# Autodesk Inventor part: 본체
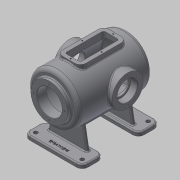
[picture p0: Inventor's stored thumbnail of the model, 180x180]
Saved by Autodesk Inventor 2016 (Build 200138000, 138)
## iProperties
Created: 2016-02
Part Number: 본체
Material: 일반
Document SubType Name: Modeling
Designer: mduedu
Density: 1 g/cm^3
Appearance: 기본값
Author: mduedu
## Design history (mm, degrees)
sketch "스케치2"
  geometry: L1 (0, 100)-(0, -100); L2 (65, -87.083)-(65, 100); L3 (65, 100)-(0, 100); A1 r 170 centre (0, 70) between (0, -100) and (65, -87.083); 2 further points
  constraints: 6 end point, 2 point on circle, 1 centre point, 1 coincident, 1 horizontal, 1 midpoint, 1 parallel, 1 point on line, 1 vertical
  dimensions: "d3" = 200 distance of L1.start L1.end; "d5" = 130 diameter of L2 L1; "d6" = 170 radius of A1
revolve "회전1" sketch "스케치2" stored, may be unused: angle "d7" = 90 deg
sketch "스케치3"
  geometry: C1 r 47.5 at (0, 0); 1 further point
  constraints: 1 centre point, 1 coincident
  dimensions: "d8" = 95 diameter of C1
extrude "돌출2" join sketch "스케치3" distance "d10" = 10; taper "d11" = 0 deg
sketch "스케치5"
  geometry: L1 (47.5, 110)-(47.5, 100) reference; L2 (47.5, 100)-(65, 100) reference; L3 (65, 100)-(65, -87.083) reference; L4 (-65, -87.083)-(-65, 100) reference; L5 (-65, 100)-(-47.5, 100) reference; L6 (-47.5, 100)-(-47.5, 110) reference; L7 (-47.5, 110)-(47.5, 110) reference; L8 (55, 85)-(55, -80.25); L9 (0, 85)-(55, 85); L10 (0, 85)-(0, -90); A1 r 170 centre (0, 70) between (-65, -87.083) and (0, -100) reference; A2 r 170 centre (0, 70) between (0, -100) and (65, -87.083) reference; A3 r 160 centre (0, 70) between (0, -90) and (55, -80.25); 1 further point
  constraints: 6 end point, 2 point on circle, 1 centre point, 1 parallel, 1 perpendicular, 1 point on line, 1 vertical
  dimensions: "d13" = 10 distance between parallel lines of L3 L8; "d14" = 10 radial gap between concentric circles of A3 A1; "d15" = 15 distance between parallel lines of L9 L2
revolve "회전2" sketch "스케치5" stored, may be unused: angle "d16" = 90 deg
hole "구멍1" diameter "d19" = 65; stored, may be unused: countersink angle "d23" = 90 deg, drill point angle "d25" = 118 deg; dims "d17" = 10, "d18" = 10, "d20" = 6, "d21" = 4, "d22" = 2, "d24" = 8
node "작업 평면1"
sketch "스케치6"
  geometry: L1 (47.5, 110)-(-47.5, 110) reference; C1 r 40 at (0, -17); 1 further point
  constraints: 1 centre point, 1 vertical alignment
  dimensions: "d27" = 80 diameter of C1; "d29" = 127 distance from line of C1.centre L1
extrude "돌출3" join sketch "스케치6" stored distance "d30" = 10; taper "d31" = 0 deg
hole "구멍2" diameter "d34" = 42; stored, may be unused: countersink angle "d38" = 90 deg, drill point angle "d40" = 118 deg; dims "d32" = 10, "d33" = 10, "d35" = 6, "d36" = 52, "d37" = 18, "d39" = 8
sketch "스케치7" dims "d41" = 65
  geometry: C1 r 40 at (0, 0) reference; 3 further points
  constraints: 2 vertical alignment, 1 coincident, 2 other
hole "구멍3" sketch "스케치7" at (0, 32.5) diameter "d43" = 3.242; stored, may be unused: countersink angle "d47" = 90 deg, drill point angle "d49" = 118 deg; dims "d44" = 11, "d45" = 13, "d46" = 18, "d48" = 13
sketch "스케치8" dims "d53" = 80
  geometry: 3 further points
  constraints: 2 vertical alignment, 1 coincident, 2 other
hole "구멍4" sketch "스케치8" at (0, 40) diameter "d56" = 3.242; stored, may be unused: countersink angle "d60" = 90 deg, drill point angle "d62" = 118 deg; dims "d57" = 11, "d58" = 13, "d59" = 18, "d61" = 13
fillet "모깎기1" dims "d66" = 10
fillet "모깎기2" dims "d67" = 3
fillet "모깎기3" dims "d68" = 0.3
chamfer "모따기1" distance "d69" = 1; stored, may be unused: second distance "d70" = 2, angle "d71" = 45 deg
node "작업 평면2"
sketch "스케치9"
  geometry: L1 (75, 100)-(-75, 100); L2 (-75, 100)-(-75, -100); L3 (-75, -100)-(75, -100); L4 (75, -100)-(75, 100); 1 further point
  constraints: 8 end point, 2 parallel, 1 horizontal, 1 perpendicular
  dimensions: "d73" = 200 distance of L3.end L1.start; "d75" = 150 distance of L2.end L3.end; "d76" = 100 distance from line of L1 point (0, 0); "d77" = 75 distance from line of L4 point (0, 0)
extrude "돌출4" join sketch "스케치9" distance "d78" = 10; taper "d79" = 0 deg
sketch "스케치10"
  geometry: L1 (-75, -100)-(75, -100) reference; L2 (75, 100)-(-75, 100) reference; L3 (0, -100)-(0, 100); L4 (-75, 100)-(-75, -100) reference; L5 (75, -100)-(75, 100) reference; L6 (-75, 0)-(75, 0); L7 (-50, -63)-(50, -63); L8 (50, -63)-(50, -55); L9 (50, -55)-(-50, -55); L10 (-50, -55)-(-50, -63); L11 (-50, 63)-(50, 63); L12 (50, 63)-(50, 55); L13 (50, 55)-(-50, 55); L14 (-50, 55)-(-50, 63); 1 further point
  constraints: 20 end point, 4 midpoint, 4 symmetric about line, 2 parallel, 1 horizontal, 1 perpendicular, 1 other
  dimensions: "d80" = 8 distance of L9.end L7.start; "d82" = 100 distance of L7.start L7.end; "d83" = 55 distance between parallel lines of L9 L6
extrude "돌출5" join sketch "스케치10" stored distance "d84" = 10; taper "d85" = 0 deg
feature "면 기울기1" dims angle "d86" = 10 deg
sketch "스케치11"
  geometry: L1 (-110, 55)-(-51.482, 55) reference; L2 (-110, -55)-(-51.482, -55) reference; L3 (-95, 55)-(-95, -55); L4 (-65, 90)-(-65, -80.25) reference; 1 further point
  constraints: 2 end point, 2 point on line, 1 perpendicular
  dimensions: "d87" = 30 distance between parallel lines of L3 L4
feature "리브1" sketch "스케치11" dims "d88" = 1, "d89" = 8, "d90" = 0, "d91" = 0, "d92" = 1, "d93" = 1
sketch "스케치12"
  geometry: L1 (-110, 55)-(-51.482, 55) reference; L2 (-110, -55)-(-51.482, -55) reference; L3 (-110, 100)-(-110, -100) reference; L4 (-120, 152)-(-120, -142) reference; L5 (-110, 45)-(-120, 45); L6 (-120, 45)-(-120, -45); L7 (-120, -45)-(-110, -45); L8 (-110, -45)-(-110, 45); 1 further point
  constraints: 8 end point, 2 parallel, 2 point on line, 1 horizontal, 1 perpendicular
  dimensions: "d94" = 10 distance between parallel lines of L7 L2; "d95" = 10 distance between parallel lines of L1 L5
extrude "돌출6" cut sketch "스케치12" stored distance "d96" = 10; taper "d97" = 0 deg
fillet "모깎기4" dims "d98" = 15
sketch "스케치13"
  geometry: C1 r 5 at (-60, -85); C2 r 5 at (60, -85); C3 r 5 at (60, 85); C4 r 5 at (-60, 85); A1 r 15 centre (-60, -85) between (-75, -85) and (-60, -100) reference; A2 r 15 centre (60, -85) between (60, -100) and (75, -85) reference; A3 r 15 centre (60, 85) between (75, 85) and (60, 100) reference; A4 r 15 centre (-60, 85) between (-60, 100) and (-75, 85) reference; 1 further point
  constraints: 4 centre point, 4 coincident, 3 equal radius
  dimensions: "d99" = 10 diameter of C1
extrude "돌출7" cut sketch "스케치13" stored distance "d101" = 10; taper "d102" = 0 deg
fillet "모깎기5" dims "d103" = 3, "d104" = 3
fillet "모깎기6" dims "d105" = 3
sketch "스케치14"
  geometry: L1 (-60, -100)-(60, -100) reference; 2 further points
  constraints: 1 vertical alignment, 1 other
  dimensions: "d106" = 15 distance from line of point (0, -85) L1
feature "엠보싱1" sketch "스케치14" dims "d3" = 200, "d5" = 130, "d6" = 170, "d14" = 10, "d107" = 0.5, "d108" = 0
node "작업 평면3"
sketch "스케치15"
  geometry: L1 (-30, 60)-(30, 60); L2 (30, 60)-(30, -60); L3 (30, -60)-(-30, -60); L4 (-30, -60)-(-30, 60); 2 further points
  constraints: 8 end point, 2 parallel, 1 horizontal, 1 midpoint, 1 perpendicular, 1 vertical alignment
  dimensions: "d110" = 60 distance of L2.end L3.end; "d112" = 60 distance from line of L3 point (0, 0); "d113" = 120 distance of L1.end L2.end
extrude "돌출8" join sketch "스케치15" stored distance "d114" = 10; taper "d115" = 0 deg
fillet "모깎기7" dims "d116" = 15
sketch "스케치16"
  geometry: L1 (-30, -45)-(-30, 45) reference; L2 (-15, 60)-(15, 60) reference; L3 (30, 45)-(30, -45) reference; L4 (15, -60)-(-15, -60) reference; L5 (15, 50)-(-15, 50); L6 (-20, 45)-(-20, -45); L7 (-15, -50)-(15, -50); L8 (20, -45)-(20, 45); A1 r 15 centre (-15, -45) between (-30, -45) and (-15, -60) reference; A2 r 15 centre (-15, 45) between (-15, 60) and (-30, 45) reference; A3 r 15 centre (15, 45) between (30, 45) and (15, 60) reference; A4 r 15 centre (15, -45) between (15, -60) and (30, -45) reference; A5 r 5 centre (-15, 45) between (-15, 50) and (-20, 45); A6 r 5 centre (-15, -45) between (-20, -45) and (-15, -50); A7 r 5 centre (15, -45) between (15, -50) and (20, -45); A8 r 5 centre (15, 45) between (20, 45) and (15, 50); 1 further point
  constraints: 8 end point, 8 point on circle, 4 centre point, 7 other
  dimensions: "d117" = 10 distance between parallel lines of L6 L1
extrude "돌출9" cut sketch "스케치16" stored distance "d118" = 10; taper "d119" = 0 deg
fillet "모깎기8" dims "d120" = 3
sketch "스케치17"
  geometry: L1 (-30, -45)-(-30, 45) reference; L2 (-15, 60)-(15, 60) reference; L3 (30, 45)-(30, -45) reference; L4 (15, -60)-(-15, -60) reference; L5 (20, -45)-(20, 45) reference; L6 (15, 50)-(-15, 50) reference; L7 (-20, 45)-(-20, -45) reference; L8 (-15, -50)-(15, -50) reference; L9 (15, 55)-(-15, 55); L10 (-25, 45)-(-25, -45); L11 (-15, -55)-(15, -55); L12 (25, -45)-(25, 45); A1 r 15 centre (-15, 45) between (-15, 60) and (-30, 45) reference; A2 r 15 centre (15, 45) between (30, 45) and (15, 60) reference; A3 r 15 centre (15, -45) between (15, -60) and (30, -45) reference; A4 r 15 centre (-15, -45) between (-30, -45) and (-15, -60) reference; A5 r 5 centre (15, -45) between (15, -50) and (20, -45) reference; A6 r 5 centre (15, 45) between (20, 45) and (15, 50) reference; A7 r 5 centre (-15, 45) between (-15, 50) and (-20, 45) reference; A8 r 5 centre (-15, -45) between (-20, -45) and (-15, -50) reference; A9 r 10 centre (-15, 45) between (-15, 55) and (-25, 45); A10 r 10 centre (-15, -45) between (-25, -45) and (-15, -55); A11 r 10 centre (15, -45) between (15, -55) and (25, -45); A12 r 10 centre (15, 45) between (25, 45) and (15, 55); 5 further points
  constraints: 8 end point, 8 point on circle, 4 centre point, 4 midpoint, 7 other
  dimensions: "d121" = 5 distance between parallel lines of L10 L1
hole "구멍5" sketch "스케치17" at (0, 55), (25, 0), (0, -55), (-25, 0) diameter "d122" = 3.242; stored, may be unused: countersink angle "d126" = 90 deg, drill point angle "d128" = 118 deg; dims "d123" = 9, "d124" = 13, "d125" = 18, "d127" = 11
fillet "모깎기9" dims "d129" = 3
node "솔리드2"
pattern_circular "원형 패턴1" dims angle "d51" = 360 deg
mirror "대칭1"
pattern_circular "원형 패턴2" dims angle "d64" = 360 deg
node "절단 모서리 투영1"
node "절단 모서리 투영2"
node "절단 모서리 투영3"
other parameters: "d26" = 75
